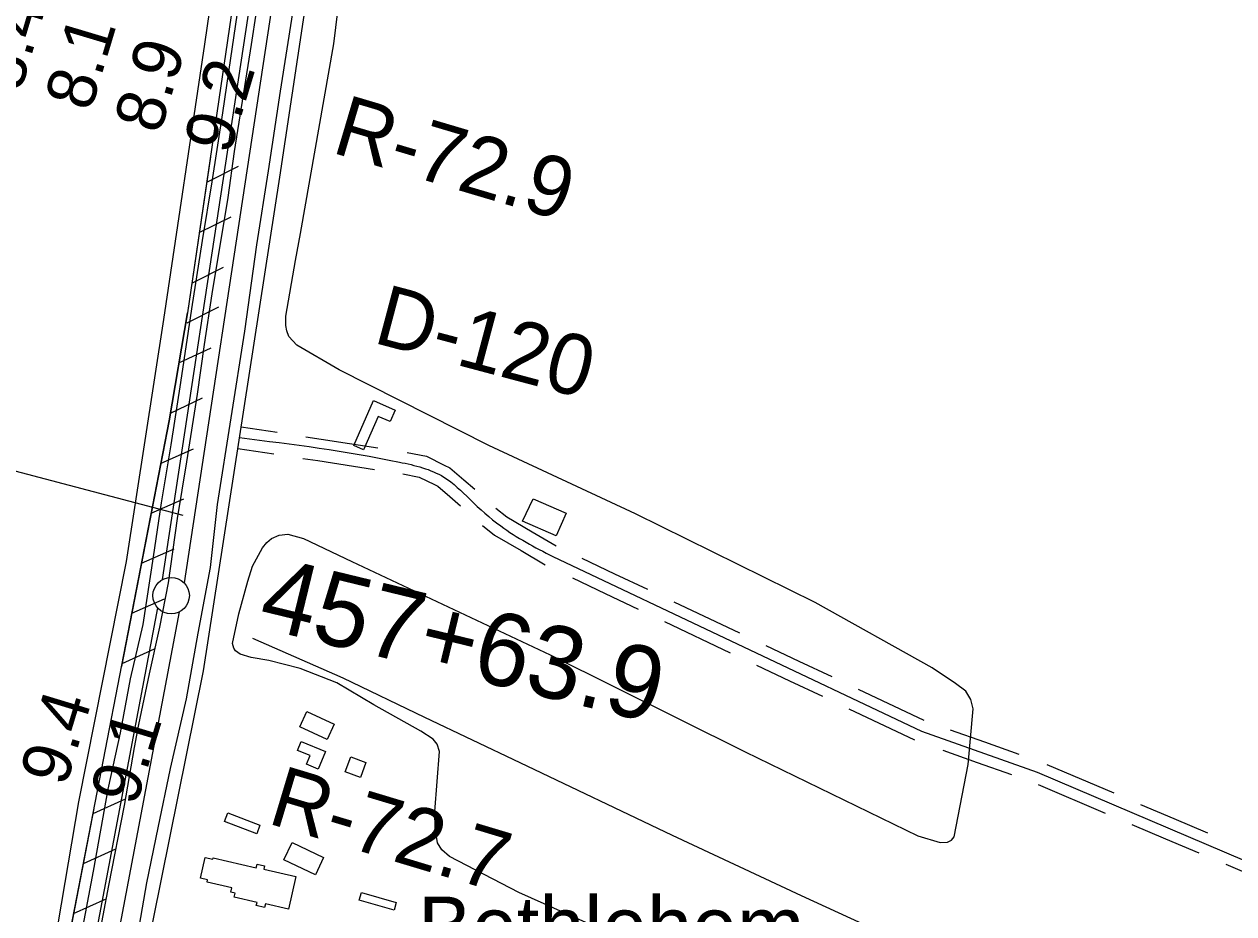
# Model space of a CAD drawing. Extents: x 3683613 to 3738215, y 469626 to 495384.
# Drawn here: x 3704159 to 3705820, y 479573 to 480796 of the extents above; entities that cross this region are included whole.
import ezdxf

# ---------------------------------------------------------------- set-up
doc = ezdxf.new("R2010")
doc.units = 0
for name, color, linetype in [('V-BLDG-OTLN', 7, 'Continuous'), ('V-FLOD-BASE', 7, 'Continuous'), ('V-LEVE-TOET', 7, 'Continuous'), ('V-RIVR-RANG', 7, 'Continuous'), ('V-RIVR-RANG-IDEN', 7, 'Continuous'), ('V-ROAD-CNTR', 7, 'Continuous'), ('V-RRAP-FSHR', 7, 'Continuous'), ('V-SITE-OTLN-IDEN', 7, 'Continuous'), ('V-SITE-VEGE', 7, 'Continuous'), ('V-SURV-IDEN', 7, 'Continuous'), ('V-SURV-LINE', 7, 'Continuous'), ('V-TOPO-SHOR', 7, 'Continuous')]:
    doc.layers.add(name, color=color, linetype=linetype)

msp = doc.modelspace()

# ---------------------------------------------------------------- linework, layer by layer
at = {"layer": 'V-BLDG-OTLN'}
for points in [[(3704611.3, 480216.8), (3704638.5, 480278.5), (3704668.3, 480265.3), (3704661.3, 480249.5), (3704644.9, 480256.7), (3704624.7, 480210.9)], [(3704857.7, 480143.5), (3704902.8, 480123.8), (3704889.3, 480092.7), (3704843.2, 480112.7)], [(3704546.8, 479851.3), (3704584.3, 479834), (3704574.6, 479812.9), (3704537, 479830.1)], [(3704539.2, 479810.3), (3704572.6, 479796.4), (3704562.5, 479772.1), (3704546.3, 479778.9), (3704551.3, 479790.7), (3704534.1, 479797.9)], [(3704607.3, 479789), (3704628, 479781.2), (3704620.4, 479760.7), (3704599.6, 479768.6)], [(3704438.4, 479712.1), (3704482.4, 479695.1), (3704477.9, 479683.2), (3704433.8, 479700.2)], [(3704569.9, 479650.8), (3704558.5, 479626.8), (3704515.2, 479647.4), (3704526.6, 479671.4)], [(3704418, 479650.4), (3704477.4, 479636.6), (3704478.6, 479641.6), (3704488.8, 479639.2), (3704487.8, 479634.8), (3704531.8, 479624.6), (3704521.4, 479579.7), (3704490, 479587), (3704488.8, 479582.1), (3704477.4, 479584.7), (3704478.4, 479589), (3704447, 479596.3), (3704448.3, 479601.9), (3704442.5, 479603.3), (3704443.9, 479609.1), (3704409.7, 479617), (3704410.4, 479620.1), (3704400.7, 479622.4), (3704407.2, 479650.8), (3704417.6, 479648.4)], [(3704618.7, 479592.2), (3704621.7, 479602.9), (3704669.6, 479589), (3704666.6, 479578.4)]]:
    msp.add_lwpolyline(points, close=True, dxfattribs=at)
at = {"layer": 'V-FLOD-BASE'}
msp.add_lwpolyline([(3704484, 480857.6), (3704470.3, 480767.7), (3704446.9, 480620.6), (3704438.1, 480557.5), (3704416.4, 480425), (3704405.8, 480355.7), (3704396, 480287.4), (3704381.3, 480194.1), (3704368.9, 480116.4), (3704356.1, 480027.9), (3704344.2, 479967.2), (3704330.2, 479903.3), (3704315.7, 479833.6), (3704309.6, 479801.7), (3704295.8, 479722), (3704274.2, 479612.2), (3704259, 479529.8), (3704233.1, 479389.2), (3704215.7, 479296), (3704198.9, 479207), (3704179.5, 479105.4), (3704158, 478991.1)], dxfattribs=at)
at = {"layer": 'V-LEVE-TOET'}
for points in [[(3704453, 480823.4), (3704442, 480749), (3704430.8, 480673.7), (3704416.4, 480579.1), (3704402.8, 480498.2), (3704388.3, 480404.7), (3704373.4, 480303.5), (3704360.1, 480217.5), (3704346.6, 480138.1), (3704335.5, 480063.8), (3704321.7, 479971), (3704304.3, 479896.2), (3704290.6, 479822.1), (3704273.4, 479744.5), (3704253.3, 479632), (3704235.9, 479540), (3704214.9, 479438), (3704199, 479342.1), (3704182.7, 479265.8), (3704167.6, 479178.6), (3704155.1, 479106.8)], [(3704527, 480810.9), (3704510.1, 480703.4), (3704493.6, 480594.1), (3704477.7, 480492.4), (3704461, 480373.9), (3704423.7, 480135.5), (3704413.8, 480049), (3704397.1, 479959.1), (3704381.1, 479868.6), (3704359, 479773.1), (3704341.9, 479691.7), (3704326.4, 479615.9), (3704312.3, 479534), (3704291.5, 479424.4), (3704275.5, 479337.1), (3704262.9, 479253.9), (3704244.7, 479159), (3704226.9, 479062.1), (3704213.4, 478985.4), (3704193.8, 478883.6), (3704173.1, 478772.8), (3704155.4, 478671.7)]]:
    msp.add_lwpolyline(points, dxfattribs=at)
at = {"layer": 'V-RIVR-RANG'}
msp.add_line((3704376.9, 480120.7), (3703313.1, 480400.7), dxfattribs=at)
at = {"layer": 'V-ROAD-CNTR'}
for points in [[(3704509.6, 480585.2), (3704633.4, 481407.9), (3704785, 482403.4), (3704837.4, 482796)], [(3703726.6, 476963.3), (3703726.6, 476963.3), (3704073.6, 478169.6), (3704082.9, 478208.9), (3704324.3, 479507.4), (3704405, 479907.3), (3704509.6, 480585.2)], [(3704456.7, 480242.4), (3704506.1, 480234.9)], [(3704545.6, 480228.8), (3704566.4, 480225.6), (3704644.5, 480213.6)], [(3704452.1, 480212.8), (3704501.6, 480205.2)], [(3704684.6, 480207.2), (3704711.1, 480202), (3704735.3, 480189.9)], [(3704541.1, 480199.1), (3704561.9, 480196), (3704639.9, 480184)], [(3704735.3, 480189.9), (3704743.3, 480186), (3704762.6, 480169.6), (3704777.4, 480156.8)], [(3704678.8, 480177.7), (3704701.3, 480173.3), (3704722, 480163.1)], [(3704722, 480163.1), (3704726.7, 480160.7), (3704743.1, 480146.8), (3704757.8, 480134.1)], [(3704806.6, 480130.5), (3704821.6, 480118.7), (3704856.5, 480098.2), (3704889.5, 480078.7)], [(3704788, 480106.9), (3704804.6, 480093.8), (3704841.3, 480072.3), (3704874.3, 480052.8)], [(3704884.6, 480064.2), (3704884.6, 480064.2), (3705391, 479824.3)], [(3704924.4, 480062), (3704969.6, 480040.6)], [(3704969.6, 480040.6), (3705014.8, 480019.2)], [(3704911.5, 480034.8), (3704956.7, 480013.4)], [(3704956.7, 480013.4), (3705001.9, 479992)], [(3705050.9, 480002), (3705141.3, 479959.2)], [(3705038.1, 479974.9), (3705128.4, 479932.1)], [(3705177.4, 479942.1), (3705222.6, 479920.7)], [(3705222.6, 479920.7), (3705267.8, 479899.3)], [(3705164.6, 479915), (3705209.8, 479893.6)], [(3705209.8, 479893.6), (3705255, 479872.2)], [(3705304, 479882.2), (3705394.3, 479839.4)], [(3705291.1, 479855.1), (3705381.5, 479812.3)], [(3705391, 479824.3), (3705549.8, 479768.1), (3706326.8, 479437.1)], [(3705430.5, 479826.3), (3705477.6, 479809.6)], [(3705477.6, 479809.6), (3705524.7, 479792.9)], [(3705420.5, 479798), (3705467.6, 479781.3)], [(3705467.6, 479781.3), (3705514.7, 479764.6)], [(3705563.1, 479778.7), (3705655.1, 479739.5)], [(3705551.4, 479751.1), (3705643.4, 479711.9)], [(3705691.9, 479723.8), (3705737.9, 479704.2)], [(3705737.9, 479704.2), (3705783.9, 479684.6)], [(3705680.2, 479696.2), (3705726.2, 479676.6)], [(3705726.2, 479676.6), (3705772.2, 479657)], [(3705809, 479641.4), (3705901, 479602.2)]]:
    msp.add_lwpolyline(points, dxfattribs=at)
msp.add_spline([(3704454.4, 480227.6), (3704673.9, 480194), (3704735, 480173.3), (3704770.6, 480142.9), (3704813.1, 480106.2), (3704884.6, 480064.2)], degree=3, dxfattribs=at)
at = {"layer": 'V-RRAP-FSHR'}
for p, q in [((3704409.3, 480578.4), (3704452.9, 480600.3)), ((3704399.1, 480509.2), (3704442.7, 480531.1)), ((3704388.9, 480439.9), (3704432.5, 480461.8)), ((3704382.3, 480385.4), (3704426, 480407.3)), ((3704371.2, 480330.2), (3704415.3, 480351.1)), ((3704359.6, 480261.2), (3704403.7, 480282.1)), ((3704346.5, 480192.4), (3704391.1, 480212.3)), ((3704333.1, 480123.7), (3704377.7, 480143.6)), ((3704319.8, 480055), (3704364.4, 480074.8)), ((3704306.5, 479986.3), (3704351.1, 480006.1)), ((3704293.1, 479917.5), (3704337.7, 479937.4)), ((3704253.1, 479711.4), (3704297.7, 479731.3)), ((3704239.8, 479642.7), (3704284.4, 479662.5)), ((3704226.4, 479573.9), (3704271, 479593.8))]:
    msp.add_line(p, q, dxfattribs=at)
for points in [[(3706323.9, 485767.8), (3705976, 485252.8), (3705840.7, 485020.2), (3705315.8, 484071), (3704796.5, 483151.4), (3704698.6, 482470), (3704526.4, 481375.3), (3704382.9, 480399.2)], [(3704414.4, 480613.5), (3704382.9, 480399.2)], [(3702858, 475214.9), (3703006.6, 475446.7), (3703078, 475579.2), (3703285.6, 476047.1), (3703546.8, 476749.7), (3703611.7, 476939), (3703915.1, 478011.5), (3703976.8, 478214.3), (3704202.3, 479449.5), (3704357.8, 480250.5), (3704382.9, 480399.2)], [(3704382.9, 480399.2), (3704357.8, 480250.5), (3704292.3, 479913.3)], [(3704254.4, 479717.9), (3704202.3, 479449.5), (3704110.7, 478948)]]:
    msp.add_lwpolyline(points, dxfattribs=at)
at = {"layer": 'V-SITE-VEGE'}
for p, q in [((3704584, 480768.5), (3704608.1, 480964.4)), ((3704538, 480507.9), (3704584, 480768.5)), ((3704531.1, 480470.9), (3704538, 480507.9)), ((3704517.9, 480394.6), (3704531.1, 480470.9)), ((3704517.8, 480381.4), (3704517.9, 480394.6)), ((3704519.4, 480374.5), (3704517.8, 480381.4)), ((3704522, 480366.5), (3704519.4, 480374.5)), ((3704533.1, 480354.6), (3704522, 480366.5)), ((3704591, 480320.7), (3704533.1, 480354.6)), ((3704796.7, 480216.7), (3704591, 480320.7)), ((3704998.1, 480122.7), (3704796.7, 480216.7)), ((3705245, 480001.1), (3704998.1, 480122.7)), ((3704491.8, 480083.7), (3704498.3, 480089.1)), ((3704498.3, 480089.1), (3704508.7, 480093.5)), ((3704508.7, 480093.5), (3704520.8, 480094.8)), ((3704520.8, 480094.8), (3704542.2, 480089)), ((3704542.2, 480089), (3704608.4, 480057.4)), ((3704472, 480051.2), (3704485.7, 480076.3)), ((3704485.7, 480076.3), (3704491.8, 480083.7)), ((3704608.4, 480057.4), (3704880.9, 479929.2)), ((3704465.9, 480030.2), (3704472, 480051.2)), ((3704453.6, 479985.7), (3704465.9, 480030.2)), ((3705405.8, 479911.4), (3705245, 480001.1)), ((3704444.5, 479944.7), (3704453.6, 479985.7)), ((3704446.7, 479938.2), (3704444.5, 479944.7)), ((3704448.9, 479934.7), (3704446.7, 479938.2)), ((3704455.2, 479930.3), (3704448.9, 479934.7)), ((3704470.3, 479925.5), (3704455.2, 479930.3)), ((3704494.4, 479921.5), (3704470.3, 479925.5)), ((3704537.5, 479910.3), (3704494.4, 479921.5)), ((3704880.9, 479929.2), (3705148.9, 479795.9)), ((3704587.8, 479890.8), (3704537.5, 479910.3)), ((3705438, 479889.9), (3705405.8, 479911.4)), ((3704638.6, 479860.3), (3704587.8, 479890.8)), ((3705451.8, 479879.4), (3705438, 479889.9)), ((3705459.1, 479867.7), (3705451.8, 479879.4)), ((3704703.2, 479824.1), (3704638.6, 479860.3)), ((3705455.1, 479778.4), (3705462.1, 479855.2)), ((3705462.1, 479855.2), (3705459.1, 479867.7)), ((3704720.1, 479813.4), (3704703.2, 479824.1)), ((3704725.9, 479806.5), (3704720.1, 479813.4)), ((3704728.9, 479796.5), (3704725.9, 479806.5)), ((3704722.7, 479714.2), (3704728.9, 479796.5)), ((3705148.9, 479795.9), (3705386.3, 479680.4)), ((3705435.8, 479679.1), (3705455.1, 479778.4)), ((3704722.9, 479690.8), (3704722.7, 479714.2)), ((3704726.2, 479670.7), (3704722.9, 479690.8)), ((3705386.3, 479680.4), (3705416.8, 479671.3)), ((3705416.8, 479671.3), (3705426.6, 479671.9)), ((3705426.6, 479671.9), (3705432.4, 479674.5)), ((3705432.4, 479674.5), (3705435.8, 479679.1)), ((3704732.3, 479661.5), (3704726.2, 479670.7)), ((3704742.6, 479652.3), (3704732.3, 479661.5)), ((3704837.8, 479602.5), (3704742.6, 479652.3)), ((3705077.4, 479496.1), (3704837.8, 479602.5))]:
    msp.add_line(p, q, dxfattribs=at)
msp.add_lwpolyline([(3704465.9, 481177.2), (3704406.1, 480767.9), (3704350, 480389.8), (3704298.4, 480057.3), (3704233.3, 479727.1), (3704180.9, 479419.3), (3704161.5, 479328.4), (3704149.5, 479294.8)], dxfattribs=at)
at = {"layer": 'V-SURV-LINE'}
for points in [[(3704348.6, 480032.5), (3704552.8, 481375.5)], [(3704582.5, 481371), (3704378.3, 480028)], [(3704010.6, 478243.3), (3704342, 479993.7)], [(3704371.5, 479988.1), (3704040, 478237.7)]]:
    msp.add_lwpolyline(points, dxfattribs=at)
msp.add_circle((3704360.4, 480010.5), 25, dxfattribs=at)
at = {"layer": 'V-TOPO-SHOR'}
msp.add_lwpolyline([(3704472.2, 479952.2), (3704596.4, 479897.8), (3704708.5, 479843.6), (3704839.6, 479781.1), (3705048.4, 479681.4), (3705225.9, 479598.8), (3705401.2, 479517.9), (3705570, 479434.6), (3705771.3, 479339.3), (3705970.5, 479247.2)], dxfattribs=at)

# ---------------------------------------------------------------- texts
at = {"layer": 'V-RIVR-RANG'}
for s, rotation, p in [('8.4', 73.3083, (3704153, 480700.2)), ('8.1', 73.3083, (3704249.6, 480674)), ('8.9', 73.3083, (3704344.7, 480643)), ('9.2', 73.3083, (3704440.6, 480614.8)), ('9.4', 73.1183, (3704215.5, 479746.6)), ('9.1', 73.1183, (3704312, 479720))]:
    msp.add_text(s, height=67, rotation=rotation, dxfattribs=at).set_placement(p)
at = {"layer": 'V-RIVR-RANG-IDEN'}
for s, rotation, p in [('R-72.9', 343.4522, (3704579.1, 480619.7)), ('D-120', 345.1093, (3704636.1, 480358.5)), ('R-72.7', 343.2559, (3704491, 479698.3))]:
    msp.add_text(s, height=83, rotation=rotation, dxfattribs=at).set_placement(p)
at = {"layer": 'V-SITE-OTLN-IDEN'}
msp.add_text('Bethlehem', height=83, dxfattribs=at).set_placement((3704699.6, 479514.2))
at = {"layer": 'V-SURV-IDEN'}
msp.add_text('457+63.9', height=100, rotation=346.3476, dxfattribs=at).set_placement((3704477.3, 479967.6))

doc.saveas('drawing.dxf')
